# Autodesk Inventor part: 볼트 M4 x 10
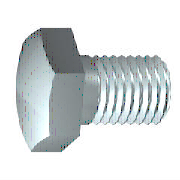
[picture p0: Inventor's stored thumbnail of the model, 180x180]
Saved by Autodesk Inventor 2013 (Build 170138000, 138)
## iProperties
Created: 2012-02
Part Number: 볼트 M4 x 10
Material: 스테인리스강
Description: 6각 머리 나사
Document SubType Name: Modeling
Standard: ISO 4017
Designer: mduedu
Standard Revision: Third edition 1999-08-15
Standards Organization: ISO
Language: ko-KR
Size Designation: M4 x 10
Categories: <MemberInstance><Categories><Category DisplayName="조임쇠" InternalName="e4da775c-781d-43d5-af7c-5136215cf5a6" Mnemonic="FSTN"><Category DisplayName="볼트" InternalN
Density: 8.08 g/cm^3
IsCustomPart: 0
Author: mduedu
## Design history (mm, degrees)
sketch "스케치1"
  geometry: L1 (0, 3.015)-(0, 2); L2 (2.1, 2)-(10, 2); L3 (10, 2)-(10, 0); L4 (10, 0)-(-0.4, 0); L5 (-2.48, 0)-(12.08, 0) reference; L6 (-0.4, 0)-(-0.4, 3.015); L7 (-0.4, 3.015)-(0, 3.015); L8 (2.1, 2)-(1.67, 2); L9 (1.67, 2)-(0, 2); L10 (0, -0.603)-(0, 3.618) reference
  constraints: 16 end point, 2 collinear, 2 perpendicular, 1 parallel
  dimensions: "d0" = 10 distance between parallel lines of L3 L1 (= NLG); "d1" = 7.9 distance from line of L2.start L3 (= GEL); "d2" = 4 diameter of L2 L4 (= GD); "d9" = 0.4001 distance between parallel lines of L6 L1 (computed from SD); "d10" = 6.03 diameter of L7 L4 (= SD2); "d13" = 0.42952 distance of L2.start L8.end (computed from GAL); "d14" = 4 diameter of L9 L4 (= BDM)
revolve "본체" sketch "스케치1" stored, may be unused: angle "d12" = 90 deg
sketch "스케치2"
  geometry: L1 (0, 4.041)-(3.5, 2.021); L2 (3.5, 2.021)-(3.5, -2.021); L3 (3.5, -2.021)-(0, -4.041); L4 (0, -4.041)-(-3.5, -2.021); L5 (-3.5, -2.021)-(-3.5, 2.021); L6 (-3.5, 2.021)-(0, 4.041); 2 further points
  constraints: 12 end point, 1 coincident, 1 vertical, 11 other
  dimensions: "d11" = 7 distance between parallel lines of L5 L2 (= SW)
extrude "머리" join sketch "스케치2" distance "d3" = 2.4 (= KOH - SD); taper "d4" = 0 deg
sketch "스케치4"
  geometry: L1 (-2.8, 3.5)-(-2.8, 4.041); L2 (-2.8, 4.041)-(-2.487, 4.041); L3 (-2.487, 4.041)-(-2.8, 3.5); L4 (-3.28, 0)-(0.08, 0) reference; L5 (-0.4, 4.041)-(-2.8, 4.041) reference; L6 (-2.8, 2.021)-(-2.8, 4.041) reference
  constraints: 6 end point, 2 collinear, 1 perpendicular, 1 vertical
  dimensions: "d5" = 30 deg angle of L3 L1 (= ANG1); "d19" = 7 diameter of L1.start L4 (= SW0)
revolve "모따기1" sketch "스케치4" stored, may be unused: angle "d21" = 90 deg
workplane "Work Plane1"
body "Solid1"
feature "스레드" dims "d15" = 7.9 (= GEL), "d16" = 0
chamfer "모따기2" distance "d6" = 0.42941 (= -0.5 x SPD + 0.5 x GD); stored, may be unused: second distance "d7" = 0.42952 (computed from GUL), angle "d55" = 45 deg
other parameters: "NLG" = 10 [user parameter; used in 1 equation term], "GD" = 4 (= NND) [user parameter; used in 2 equation terms], "BDM" = 4 (= NND) [user parameter; used in 1 equation term], "KOH" = 2.8 [user parameter; used in 1 equation term], "GEL" = 7.9 [user parameter; used in 2 equation terms], "SW" = 7 [user parameter; used in 2 equation terms], "SW0" = 7 (= SW) [user parameter; used in 1 equation term], "SPD" = 3.14117 (= NND - 1.2269 x PTC) [user parameter; used in 1 equation term], "SD2" = 6.03 [user parameter; used in 2 equation terms], "SD" = 0.4 [user parameter; used in 2 equation terms], "ANG1" = 30 deg [user parameter; used in 1 equation term], "GAL" = 0.42941 (= 0.61345 x PTC) [user parameter; used in 1 equation term], "GUL" = 0.42941 (= 0.61345 x PTC) [user parameter; used in 1 equation term], "d8" = 0, "RR" = 0.2 [user parameter], "d57" = 0, "d58" = 0, "TPU" = 14.28571 (computed from PTC) [user parameter], "GD1" = 3.14117 (= THREADDIA - 1.2269 x PTC) [user parameter], "THREADDIA" = 4 [user parameter; used in 1 equation term], "SDH" = 6.03 (= SD2) [user parameter], "SDHG" = 2.1 [user parameter], "TOA" = 30 deg [user parameter], "PTC" = 0.7 [user parameter; used in 5 equation terms], "NND" = 4 [user parameter; used in 3 equation terms], "E0" = 8.085 [user parameter]
